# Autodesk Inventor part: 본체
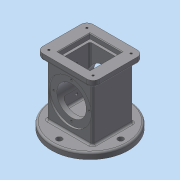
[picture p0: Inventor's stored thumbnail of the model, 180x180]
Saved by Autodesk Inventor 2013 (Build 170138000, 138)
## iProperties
Created: 2018-10
Part Number: 본체
Material: 일반
Document SubType Name: Modeling
Designer: Gpr
Density: 1 g/cm^3
Author: Gpr
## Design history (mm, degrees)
sketch "스케치1"
  geometry: L1 (37, -33)-(-37, -33); L2 (-37, -33)-(-37, 33); L3 (-37, 33)-(37, 33); L4 (37, 33)-(37, -33); L5 (37, -33)-(-37, 33); L6 (-37, -33)-(37, 33); 1 further point
  constraints: 12 end point, 2 midpoint, 2 parallel, 1 horizontal, 1 perpendicular
  dimensions: "d0" = 74 distance of L2.end L3.end; "d2" = 66 distance of L3.end L1.start
extrude "돌출1" new body sketch "스케치1" stored distance "d3" = 108; taper "d4" = 0 deg
sketch "스케치2"
  geometry: L1 (-37, -33)-(37, -33) reference; L2 (37, -33)-(37, 33) reference; L3 (37, 33)-(-37, 33) reference; L4 (-37, 33)-(-37, -33) reference; L5 (46, -41)-(-46, -41); L6 (-46, -41)-(-46, 41); L7 (-46, 41)-(46, 41); L8 (46, 41)-(46, -41); L9 (46, -41)-(-46, 41); L10 (-46, -41)-(46, 41); 3 further points
  constraints: 12 end point, 3 midpoint, 2 parallel, 1 coincident, 1 horizontal, 1 perpendicular
  dimensions: "d5" = 92 distance of L6.end L7.end; "d7" = 82 distance of L7.end L5.start
extrude "돌출2" join sketch "스케치2" distance "d8" = 10; taper "d9" = 0 deg
sketch "스케치3"
  geometry: L1 (26, -26)-(-26, -26); L2 (-26, -26)-(-26, 26); L3 (-26, 26)-(26, 26); L4 (26, 26)-(26, -26); L5 (26, -26)-(-26, 26); L6 (-26, -26)-(26, 26); 1 further point
  constraints: 12 end point, 2 midpoint, 2 parallel, 1 horizontal, 1 perpendicular
  dimensions: "d10" = 52 distance of L2.end L3.end; "d12" = 52 distance of L3.end L1.start
extrude "돌출3" cut sketch "스케치3" distance "d13" = 8; taper "d14" = 0 deg
sketch "스케치4"
  geometry: L1 (22, -22)-(-22, -22); L2 (-22, -22)-(-22, 22); L3 (-22, 22)-(22, 22); L4 (22, 22)-(22, -22); L5 (22, -22)-(-22, 22); L6 (-22, -22)-(22, 22); 1 further point
  constraints: 12 end point, 2 midpoint, 2 parallel, 1 horizontal, 1 perpendicular
  dimensions: "d15" = 44 distance of L2.end L3.end; "d17" = 44 distance of L3.end L1.start
extrude "돌출4" cut sketch "스케치4" distance "d18" = 74; taper "d19" = 0 deg
fillet "모깎기1" dims "d20" = 3
fillet "모깎기2" dims "d21" = 3
chamfer "모따기1" distance "d22" = 1; stored, may be unused: second distance "d23" = 2, angle "d24" = 45 deg
sketch "스케치5"
  geometry: L1 (0, 0)-(74, 0) reference; C1 r 35 at (37, -54); 2 further points
  constraints: 1 centre point, 1 midpoint, 1 vertical alignment
  dimensions: "d25" = 54 distance from line of L1 C1.centre; "d26" = 70 diameter of C1
extrude "돌출5" cut sketch "스케치5" distance "d27" = 3; taper "d28" = 0 deg
sketch "스케치6"
  geometry: 1 further point
hole "구멍1" sketch "스케치6" at (37, 54) diameter "d29" = 48; stored, may be unused: countersink angle "d33" = 90 deg, drill point angle "d35" = 118 deg; dims "d30" = 6, "d31" = 70, "d32" = 3, "d34" = 8
sketch "스케치7"
  geometry: C1 r 24 at (0, 0) reference; 1 further point
  constraints: 1 vertical alignment
  dimensions: "d36" = 29 distance of C1.centre point (0, -29)
hole "구멍2" sketch "스케치7" at (0, -29) diameter "d37" = 3.242; stored, may be unused: countersink angle "d41" = 90 deg, drill point angle "d43" = 118 deg; dims "d38" = 4, "d39" = 70, "d40" = 3, "d42" = 6
sketch "스케치8"
  geometry: L1 (-37, -33)-(37, -33) reference; L2 (37, -33)-(37, 33) reference; L3 (37, 33)-(-37, 33) reference; L4 (-37, 33)-(-37, -33) reference; C1 r 62.5 at (0, 0); 1 further point
  constraints: 1 centre point, 1 coincident
  dimensions: "d47" = 125 diameter of C1
extrude "돌출6" join sketch "스케치8" distance "d49" = 10; taper "d50" = 0 deg
sketch "스케치9"
  geometry: C1 r 62.5 at (0, 0) reference; 1 further point
  constraints: 1 vertical alignment
  dimensions: "d51" = 50 distance of C1.centre point (0, 50)
hole "구멍3" sketch "스케치9" at (0, 50) diameter "d52" = 9; stored, may be unused: countersink angle "d56" = 90 deg, drill point angle "d58" = 0 deg; dims "d53" = 4, "d54" = 70, "d55" = 3, "d57" = 6
fillet "모깎기3" dims "d62" = 3
sketch "스케치10"
  geometry: L1 (36, -31)-(-36, -31); L2 (-36, -31)-(-36, 31); L3 (-36, 31)-(36, 31); L4 (36, 31)-(36, -31); L5 (36, -31)-(-36, 31); L6 (-36, -31)-(36, 31); 5 further points
  constraints: 12 end point, 4 coincident, 2 midpoint, 2 parallel, 1 horizontal, 1 perpendicular
  dimensions: "d63" = 72 distance of L2.end L3.end; "d65" = 62 distance of L3.end L1.start
hole "구멍4" sketch "스케치10" at (-36, 31), (36, 31), (36, -31), (-36, -31) diameter "d66" = 3.242; stored, may be unused: countersink angle "d70" = 90 deg, drill point angle "d72" = 118 deg; dims "d67" = 4, "d68" = 70, "d69" = 3, "d71" = 6
fillet "모깎기4" dims "d73" = 10
fillet "모깎기5" dims "d74" = 3
sketch "스케치11"
  geometry: L1 (-10, -32.5)-(-10, 92.5) reference; 3 further points
  constraints: 2 horizontal alignment
  dimensions: "d75" = 43 distance of point (27, 30) point (70, 30); "d77" = 37 distance from line of L1 point (27, 30)
hole "구멍5" sketch "스케치11" diameter "d78" = 4.134; stored, may be unused: countersink angle "d82" = 90 deg, drill point angle "d84" = 0 deg; dims "d79" = 4, "d80" = 70, "d81" = 3, "d83" = 6
hole "구멍6" sketch "스케치11" diameter "d85" = 4.134; stored, may be unused: countersink angle "d89" = 90 deg, drill point angle "d91" = 0 deg; dims "d86" = 4, "d87" = 70, "d88" = 3, "d90" = 6
sketch "스케치12"
  geometry: L1 (0, 0)-(72, 0) reference; L2 (82, 0)-(82, 10) reference; 2 further points
  constraints: 1 other
  dimensions: "d92" = 4 distance from line of L1 point (36, 4); "d93" = 46 distance from line of point (36, 4) L2
feature "엠보싱1" sketch "스케치12" dims "d0" = 74, "d2" = 66, "d8" = 10, "d9" = 0, "d94" = 0.5, "d95" = 0
fillet "모깎기6" dims "d96" = 3
sketch "스케치13"
  geometry: C1 r 62.5 at (0, 0) reference; C2 r 28 at (0, 0)
  constraints: 1 centre point, 1 coincident
  dimensions: "d97" = 56 diameter of C2
extrude "돌출7" cut sketch "스케치13" distance "d99" = 18; taper "d100" = -10 deg
fillet "모깎기7" dims "d101" = 3
fillet "모깎기8" dims "d102" = 3
node "솔리드1"
pattern_circular "원형 패턴1" dims angle "d45" = 360 deg
mirror "대칭1"
pattern_circular "원형 패턴2" dims angle "d60" = 360 deg
